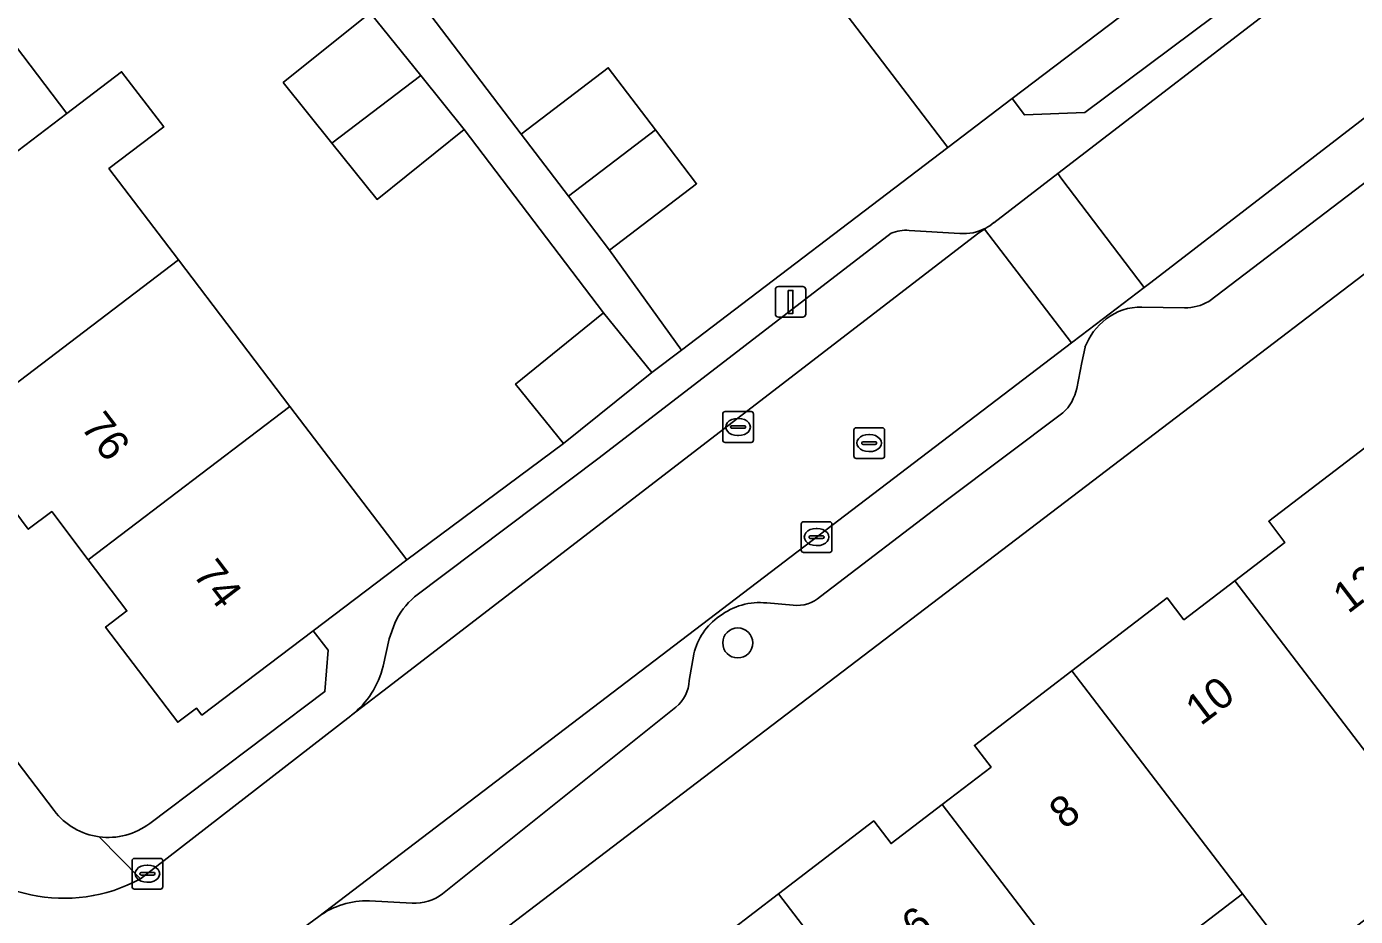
# Model space of a CAD drawing. Extents: x 160030 to 160839, y 385325 to 386450.
# Drawn here: x 160400.27 to 160443.58, y 385625.28 to 385654.28 of the extents above; entities that cross this region are included whole.
import ezdxf

# ---------------------------------------------------------------- set-up
doc = ezdxf.new("R2010")
doc.units = 0
for name, color, linetype in [('IMGEO_Boom', 7, 'Continuous'), ('IMGEO_Erf', 7, 'Continuous'), ('IMGEO_Kolk', 7, 'Continuous'), ('IMGEO_Lichtmast', 7, 'Continuous'), ('IMGEO_Muur', 7, 'Continuous'), ('IMGEO_Pand', 7, 'Continuous'), ('IMGEO_Pand_nummerreeks', 7, 'Continuous'), ('IMGEO_Parkeervlak_open', 7, 'Continuous'), ('IMGEO_Rijbaan_lokaal_open', 7, 'Continuous'), ('IMGEO_Rioolput', 7, 'Continuous'), ('IMGEO_Voetpad_open', 7, 'Continuous')]:
    doc.layers.add(name, color=color, linetype=linetype)

msp = doc.modelspace()

# ---------------------------------------------------------------- linework, layer by layer
at = {"layer": 'IMGEO_Boom'}
msp.add_circle((160423.447, 385634.193), 0.489, dxfattribs=at)
at = {"layer": 'IMGEO_Erf'}
for points in [[(160339.544, 385709.767), (160401.163, 385628.731)], [(160404.686, 385666.157), (160416.39, 385650.779), (160419.228, 385652.939), (160420.771, 385650.912), (160422.106, 385649.158), (160419.268, 385646.998), (160421.608, 385643.74), (160430.292, 385650.339), (160426.523, 385655.289)], [(160460.162, 385658.643), (160410.315, 385620.656)], [(160397.949, 385656.227), (160401.582, 385651.452), (160403.367, 385652.81), (160404.736, 385651.012), (160402.95, 385649.654), (160405.215, 385646.677), (160408.849, 385641.902), (160412.656, 385636.898), (160417.77, 385640.691), (160416.205, 385642.632), (160419.075, 385644.947), (160414.527, 385650.928), (160411.69, 385648.65), (160410.218, 385650.483), (160408.634, 385652.455), (160411.471, 385654.733)], [(160436.916, 385655.382), (160432.39, 385651.936), (160432.792, 385651.4), (160434.761, 385651.485), (160440.362, 385655.672)], [(160404.281, 385628.312), (160409.991, 385632.61), (160410.095, 385633.957), (160409.605, 385634.586), (160405.98, 385631.84), (160405.805, 385632.07), (160405.195, 385631.608), (160402.844, 385634.71), (160403.54, 385635.237), (160402.278, 385636.903), (160401.086, 385638.476), (160400.325, 385637.9), (160397.921, 385641.128), (160395.647, 385644.183), (160396.275, 385644.66), (160394.949, 385646.406), (160393.774, 385647.952), (160393.149, 385647.476), (160390.694, 385650.708), (160388.374, 385653.761), (160389.06, 385654.283)], [(160421.6, 385623.587), (160424.778, 385626.021), (160427.879, 385628.395), (160428.446, 385627.654), (160430.109, 385628.927), (160431.701, 385630.146), (160431.159, 385630.854), (160434.331, 385633.284), (160437.441, 385635.665), (160437.99, 385634.948), (160439.644, 385636.215), (160441.281, 385637.468), (160440.753, 385638.158), (160443.879, 385640.552)], [(160441.781, 385623.558), (160439.896, 385626.017), (160435.132, 385622.369)]]:
    msp.add_lwpolyline(points, dxfattribs=at)
for centre, radius, start, end in [((160402.934, 385630.08), 2.226, 217.296, 262.288), ((160402.931, 385630.075), 2.221, 262.3496, 307.4526)]:
    msp.add_arc(centre, radius, start, end, dxfattribs=at)
at = {"layer": 'IMGEO_Kolk'}
for p, q in [((160422.956, 385640.805), (160422.956, 385641.657)), ((160423.031, 385641.731), (160423.883, 385641.731)), ((160423.444, 385641.511), (160423.469, 385641.511)), ((160423.957, 385641.657), (160423.957, 385640.805)), ((160423.215, 385641.225), (160423.215, 385641.237)), ((160423.653, 385641.188), (160423.255, 385641.188)), ((160423.258, 385641.274), (160423.656, 385641.274)), ((160423.467, 385640.951), (160423.442, 385640.951)), ((160423.699, 385641.237), (160423.699, 385641.225)), ((160423.883, 385640.731), (160423.031, 385640.731)), ((160425.516, 385637.218), (160425.516, 385638.07)), ((160425.591, 385638.144), (160426.443, 385638.144)), ((160426.004, 385637.924), (160426.029, 385637.924)), ((160426.517, 385638.07), (160426.517, 385637.218)), ((160425.775, 385637.638), (160425.775, 385637.65)), ((160426.213, 385637.601), (160425.815, 385637.601)), ((160425.818, 385637.687), (160426.216, 385637.687)), ((160426.259, 385637.65), (160426.259, 385637.638)), ((160426.443, 385637.144), (160425.591, 385637.144)), ((160426.027, 385637.364), (160426.002, 385637.364)), ((160403.705, 385626.247), (160403.705, 385627.099)), ((160403.78, 385627.173), (160404.632, 385627.173)), ((160404.706, 385627.099), (160404.706, 385626.247)), ((160403.964, 385626.667), (160403.964, 385626.679)), ((160404.402, 385626.63), (160404.004, 385626.63)), ((160404.007, 385626.716), (160404.405, 385626.716)), ((160404.193, 385626.953), (160404.218, 385626.953)), ((160404.448, 385626.679), (160404.448, 385626.667)), ((160404.632, 385626.173), (160403.78, 385626.173)), ((160404.216, 385626.393), (160404.191, 385626.393))]:
    msp.add_line(p, q, dxfattribs=at)
for points in [[(160422.956, 385640.805), (160422.956, 385641.657)], [(160423.031, 385641.731), (160423.883, 385641.731)], [(160423.957, 385641.657), (160423.957, 385640.805)], [(160423.883, 385640.731), (160423.031, 385640.731)], [(160425.516, 385637.218), (160425.516, 385638.07)], [(160425.591, 385638.144), (160426.443, 385638.144)], [(160426.517, 385638.07), (160426.517, 385637.218)], [(160426.443, 385637.144), (160425.591, 385637.144)], [(160403.705, 385626.247), (160403.705, 385627.099)], [(160403.78, 385627.173), (160404.632, 385627.173)], [(160404.706, 385627.099), (160404.706, 385626.247)], [(160404.632, 385626.173), (160403.78, 385626.173)]]:
    msp.add_lwpolyline(points, dxfattribs=at)
for centre, radius, start, end in [((160423.033, 385641.655), 0.0765, 91.552, 178.448), ((160423.033, 385641.655), 0.0765, 91.552, 178.448), ((160423.881, 385641.655), 0.0765, 1.552, 88.448), ((160423.881, 385641.655), 0.0765, 1.552, 88.448), ((160423.255, 385641.234), 0.0403, 85.8775, 175.7526), ((160423.252, 385641.224), 0.0366, 178.938, 274.7102), ((160423.656, 385641.231), 0.043, 264.8664, 352.4533), ((160423.66, 385641.236), 0.0386, 1.7309, 96.639), ((160423.033, 385640.807), 0.0765, 181.552, 268.448), ((160423.033, 385640.807), 0.0765, 181.552, 268.448), ((160423.881, 385640.807), 0.0765, 271.552, 358.448), ((160423.881, 385640.807), 0.0765, 271.552, 358.448), ((160425.593, 385638.068), 0.0765, 91.552, 178.448), ((160425.593, 385638.068), 0.0765, 91.552, 178.448), ((160426.441, 385638.068), 0.0765, 1.552, 88.448), ((160426.441, 385638.068), 0.0765, 1.552, 88.448), ((160425.815, 385637.647), 0.0403, 85.8775, 175.7526), ((160425.812, 385637.637), 0.0366, 178.938, 274.7102), ((160426.216, 385637.644), 0.043, 264.8664, 352.4533), ((160426.22, 385637.649), 0.0386, 1.7309, 96.639), ((160425.593, 385637.22), 0.0765, 181.552, 268.448), ((160425.593, 385637.22), 0.0765, 181.552, 268.448), ((160426.441, 385637.22), 0.0765, 271.552, 358.448), ((160426.441, 385637.22), 0.0765, 271.552, 358.448), ((160403.782, 385627.097), 0.0765, 91.552, 178.448), ((160403.782, 385627.097), 0.0765, 91.552, 178.448), ((160404.63, 385627.097), 0.0765, 1.552, 88.448), ((160404.63, 385627.097), 0.0765, 1.552, 88.448), ((160404.004, 385626.676), 0.0403, 85.8775, 175.7526), ((160404.001, 385626.666), 0.0366, 178.938, 274.7102), ((160404.405, 385626.673), 0.043, 264.8664, 352.4533), ((160404.409, 385626.678), 0.0386, 1.7309, 96.639), ((160403.782, 385626.249), 0.0765, 181.552, 268.448), ((160403.782, 385626.249), 0.0765, 181.552, 268.448), ((160404.63, 385626.249), 0.0765, 271.552, 358.448), ((160404.63, 385626.249), 0.0765, 271.552, 358.448)]:
    msp.add_arc(centre, radius, start, end, dxfattribs=at)
for centre, major_axis, ratio, start_param, end_param in [((160423.443, 385641.231), (-0.387, 0.002), 0.722429, 4.712389, 7.853982), ((160423.468, 385641.231), (-0.39, 0.002), 0.717154, 1.570796, 4.712389), ((160426.003, 385637.644), (-0.387, 0.002), 0.722429, 4.712389, 7.853982), ((160426.028, 385637.644), (-0.39, 0.002), 0.717154, 1.570796, 4.712389), ((160404.192, 385626.673), (-0.387, 0.002), 0.722429, 4.712389, 7.853982), ((160404.217, 385626.673), (-0.39, 0.002), 0.717154, 1.570796, 4.712389)]:
    msp.add_ellipse(centre, major_axis=major_axis, ratio=ratio, start_param=start_param, end_param=end_param, dxfattribs=at)
at = {"layer": 'IMGEO_Lichtmast'}
for p, q in [((160424.673, 385644.909), (160424.673, 385645.709)), ((160424.673, 385645.709), (160424.673, 385644.909)), ((160424.773, 385645.809), (160425.563, 385645.809)), ((160425.563, 385645.809), (160424.773, 385645.809)), ((160425.663, 385645.709), (160425.663, 385644.909)), ((160425.663, 385644.909), (160425.663, 385645.709)), ((160425.563, 385644.809), (160424.773, 385644.809)), ((160424.773, 385644.809), (160425.563, 385644.809))]:
    msp.add_line(p, q, dxfattribs=at)
msp.add_lwpolyline([(160425.093, 385645.684), (160425.243, 385645.684), (160425.243, 385644.934), (160425.093, 385644.934), (160425.093, 385645.684)], dxfattribs=at)
for centre, start, end in [((160424.773, 385645.709), 90, 180), ((160424.773, 385645.709), 90, 180), ((160425.563, 385645.709), 0, 90), ((160425.563, 385645.709), 360, 90), ((160424.773, 385644.909), 180, 270), ((160424.773, 385644.909), 180, 270), ((160425.563, 385644.909), 270, 0), ((160425.563, 385644.909), 270, 0)]:
    msp.add_arc(centre, 0.1, start, end, dxfattribs=at)
at = {"layer": 'IMGEO_Muur'}
for points in [[(160421.608, 385643.74), (160430.292, 385650.339)], [(160417.77, 385640.691), (160412.656, 385636.898)]]:
    msp.add_lwpolyline(points, dxfattribs=at)
at = {"layer": 'IMGEO_Pand'}
for points in [[(160432.39, 385651.936), (160436.916, 385655.382), (160436.749, 385655.601), (160437.372, 385656.075), (160435.044, 385659.132), (160434.237, 385658.518), (160432.964, 385660.191), (160426.523, 385655.289), (160430.292, 385650.339)], [(160390.694, 385650.708), (160393.149, 385647.476), (160393.774, 385647.952), (160394.949, 385646.406), (160401.582, 385651.452), (160397.949, 385656.227)], [(160411.471, 385654.733), (160408.634, 385652.455), (160410.218, 385650.483), (160413.114, 385652.687)], [(160405.215, 385646.677), (160402.95, 385649.654), (160404.736, 385651.012), (160403.367, 385652.81), (160401.582, 385651.452), (160394.949, 385646.406), (160396.275, 385644.66), (160395.647, 385644.183), (160397.921, 385641.128)], [(160411.69, 385648.65), (160414.527, 385650.928), (160413.114, 385652.687), (160410.218, 385650.483)], [(160420.771, 385650.912), (160419.228, 385652.939), (160416.39, 385650.779), (160417.933, 385648.752)], [(160420.771, 385650.912), (160417.933, 385648.752), (160419.268, 385646.998), (160422.106, 385649.158)], [(160397.921, 385641.128), (160400.325, 385637.9), (160401.086, 385638.476), (160402.278, 385636.903), (160408.849, 385641.902), (160405.215, 385646.677)], [(160420.641, 385643.006), (160419.075, 385644.947), (160416.205, 385642.632), (160417.77, 385640.691)], [(160412.656, 385636.898), (160408.849, 385641.902), (160402.278, 385636.903), (160403.54, 385635.237), (160402.844, 385634.71), (160405.195, 385631.608), (160405.805, 385632.07), (160405.98, 385631.84), (160409.605, 385634.586)], [(160449.423, 385633.312), (160443.879, 385640.552), (160440.753, 385638.158), (160441.281, 385637.468), (160439.644, 385636.215), (160444.66, 385629.665)], [(160437.99, 385634.948), (160437.441, 385635.665), (160434.331, 385633.284), (160439.896, 385626.017), (160441.781, 385623.558), (160446.544, 385627.205), (160444.66, 385629.665), (160439.644, 385636.215)], [(160439.896, 385626.017), (160434.331, 385633.284), (160431.159, 385630.854), (160431.701, 385630.146), (160430.109, 385628.927), (160435.132, 385622.369)], [(160435.132, 385622.369), (160430.109, 385628.927), (160428.446, 385627.654), (160427.879, 385628.395), (160424.778, 385626.021), (160430.368, 385618.721)], [(160424.778, 385626.021), (160421.6, 385623.587), (160422.204, 385622.798), (160420.619, 385621.585), (160425.604, 385615.074), (160427.139, 385613.069), (160431.903, 385616.717), (160430.368, 385618.721)]]:
    msp.add_lwpolyline(points, close=True, dxfattribs=at)
at = {"layer": 'IMGEO_Parkeervlak_open'}
for points in [[(160447.596, 385654.17), (160436.906, 385645.942), (160436.696, 385645.782), (160434.639, 385644.215), (160434.322, 385643.974), (160409.789, 385625.281)], [(160438.797, 385645.324), (160446.86, 385651.459)], [(160410.858, 385631.839), (160411.883, 385632.627), (160431.304, 385647.559), (160431.485, 385647.681)], [(160428.445, 385647.548), (160418.935, 385640.223), (160412.91, 385635.694)], [(160430.685, 385647.538), (160429.033, 385647.639)], [(160431.485, 385647.681), (160431.527, 385647.709)], [(160436.619, 385645.137), (160438.011, 385645.118)], [(160434.493, 385642.488), (160434.659, 385643.332), (160434.764, 385643.83)], [(160426.142, 385635.709), (160430.242, 385638.841), (160434.038, 385641.69)], [(160424.394, 385635.498), (160425.253, 385635.428)], [(160412.267, 385634.841), (160412.086, 385634.326), (160411.892, 385633.441)], [(160421.864, 385632.967), (160422.019, 385633.833)], [(160413.828, 385626.02), (160421.431, 385632.101)], [(160411.441, 385625.789), (160412.835, 385625.713)]]:
    msp.add_lwpolyline(points, dxfattribs=at)
for centre, radius, start, end in [((160428.944, 385646.267), 1.375, 86.2988, 111.296), ((160430.815, 385649.056), 1.523, 265.1009, 297.859), ((160438.051, 385646.568), 1.451, 268.4237, 300.9486), ((160436.577, 385643.3), 1.838, 88.6797, 127.6883), ((160436.787, 385643.04), 2.172, 127.9028, 158.6755), ((160433.051, 385642.782), 1.472, 312.1282, 348.4903), ((160425.403, 385636.499), 1.081, 261.9997, 313.0823), ((160414.537, 385633.799), 2.497, 130.6411, 155.3402), ((160424.17, 385633.329), 2.18, 84.1132, 127.2374), ((160424.006, 385633.388), 2.037, 124.5608, 167.375), ((160409.095, 385634.112), 2.876, 307.8038, 346.5163), ((160420.688, 385633.014), 1.177, 309.1556, 357.7143), ((160411.36, 385623.113), 2.677, 88.2632, 125.9228), ((160412.915, 385627.214), 1.503, 266.9576, 307.4019)]:
    msp.add_arc(centre, radius, start, end, dxfattribs=at)
at = {"layer": 'IMGEO_Rijbaan_lokaal_open'}
for points in [[(160442.4, 385656.222), (160441.798, 385655.588), (160433.875, 385649.49), (160434.013, 385649.307), (160436.696, 385645.782), (160436.906, 385645.942), (160447.596, 385654.17)], [(160431.527, 385647.709), (160431.485, 385647.681), (160434.322, 385643.974), (160434.639, 385644.215), (160436.696, 385645.782), (160434.013, 385649.307), (160433.875, 385649.49)], [(160433.875, 385649.49), (160431.795, 385647.89)], [(160434.322, 385643.974), (160431.485, 385647.681), (160431.304, 385647.559), (160411.883, 385632.627), (160410.858, 385631.839), (160410.832, 385631.819), (160403.978, 385626.504)], [(160406.576, 385622.919), (160409.789, 385625.281), (160434.322, 385643.974)]]:
    msp.add_lwpolyline(points, dxfattribs=at)
for centre, radius, start, end in [((160430.852, 385648.998), 1.455, 297.6528, 310.4152), ((160401.482, 385631.116), 5.244, 217.9348, 298.4237)]:
    msp.add_arc(centre, radius, start, end, dxfattribs=at)
at = {"layer": 'IMGEO_Rioolput'}
for p, q in [((160427.229, 385640.282), (160427.229, 385641.134)), ((160427.304, 385641.208), (160428.156, 385641.208)), ((160427.717, 385640.988), (160427.742, 385640.988)), ((160428.23, 385641.134), (160428.23, 385640.282)), ((160427.488, 385640.702), (160427.488, 385640.714)), ((160427.926, 385640.665), (160427.528, 385640.665)), ((160427.531, 385640.751), (160427.929, 385640.751)), ((160427.972, 385640.714), (160427.972, 385640.702)), ((160428.156, 385640.208), (160427.304, 385640.208)), ((160427.74, 385640.428), (160427.715, 385640.428))]:
    msp.add_line(p, q, dxfattribs=at)
for points in [[(160427.229, 385640.282), (160427.229, 385641.134)], [(160427.304, 385641.208), (160428.156, 385641.208)], [(160428.23, 385641.134), (160428.23, 385640.282)], [(160428.156, 385640.208), (160427.304, 385640.208)]]:
    msp.add_lwpolyline(points, dxfattribs=at)
for centre, radius, start, end in [((160427.306, 385641.132), 0.0765, 91.552, 178.448), ((160427.306, 385641.132), 0.0765, 91.552, 178.448), ((160428.154, 385641.132), 0.0765, 1.552, 88.448), ((160428.154, 385641.132), 0.0765, 1.552, 88.448), ((160427.528, 385640.711), 0.0403, 85.8775, 175.7526), ((160427.525, 385640.701), 0.0366, 178.938, 274.7102), ((160427.929, 385640.708), 0.043, 264.8664, 352.4533), ((160427.933, 385640.713), 0.0386, 1.7309, 96.639), ((160427.306, 385640.284), 0.0765, 181.552, 268.448), ((160427.306, 385640.284), 0.0765, 181.552, 268.448), ((160428.154, 385640.284), 0.0765, 271.552, 358.448), ((160428.154, 385640.284), 0.0765, 271.552, 358.448)]:
    msp.add_arc(centre, radius, start, end, dxfattribs=at)
for centre, major_axis, ratio, start_param, end_param in [((160427.716, 385640.708), (-0.387, 0.002), 0.722429, 4.712389, 7.853982), ((160427.741, 385640.708), (-0.39, 0.002), 0.717154, 1.570796, 4.712389)]:
    msp.add_ellipse(centre, major_axis=major_axis, ratio=ratio, start_param=start_param, end_param=end_param, dxfattribs=at)
at = {"layer": 'IMGEO_Voetpad_open'}
for points in [[(160401.163, 385628.731), (160339.544, 385709.767)], [(160411.471, 385654.733), (160413.114, 385652.687), (160414.527, 385650.928), (160419.075, 385644.947), (160420.641, 385643.006), (160421.608, 385643.74), (160419.268, 385646.998), (160417.933, 385648.752), (160416.39, 385650.779), (160404.686, 385666.157)], [(160410.315, 385620.656), (160460.162, 385658.643)], [(160440.362, 385655.672), (160434.761, 385651.485), (160432.792, 385651.4), (160432.39, 385651.936), (160430.292, 385650.339), (160421.608, 385643.74), (160420.641, 385643.006), (160417.77, 385640.691), (160412.656, 385636.898), (160409.605, 385634.586), (160410.095, 385633.957), (160409.991, 385632.61), (160404.281, 385628.312)], [(160431.795, 385647.89), (160433.875, 385649.49), (160441.798, 385655.588)], [(160446.86, 385651.459), (160438.797, 385645.324)], [(160412.91, 385635.694), (160418.935, 385640.223), (160428.445, 385647.548)], [(160429.033, 385647.639), (160430.685, 385647.538)], [(160438.011, 385645.118), (160436.619, 385645.137)], [(160434.764, 385643.83), (160434.659, 385643.332), (160434.493, 385642.488)], [(160434.038, 385641.69), (160430.242, 385638.841), (160426.142, 385635.709)], [(160425.253, 385635.428), (160424.394, 385635.498)], [(160411.892, 385633.441), (160412.086, 385634.326), (160412.267, 385634.841)], [(160422.019, 385633.833), (160421.864, 385632.967)], [(160402.635, 385627.874), (160403.978, 385626.504), (160410.832, 385631.819), (160410.858, 385631.839)], [(160421.431, 385632.101), (160413.828, 385626.02)], [(160403.978, 385626.504), (160402.635, 385627.874)], [(160412.835, 385625.713), (160411.441, 385625.789)]]:
    msp.add_lwpolyline(points, dxfattribs=at)
for centre, radius, start, end in [((160430.852, 385648.998), 1.455, 297.6528, 310.4152), ((160428.944, 385646.267), 1.375, 86.2988, 111.296), ((160430.815, 385649.056), 1.523, 265.1009, 297.859), ((160438.051, 385646.568), 1.451, 268.4237, 300.9486), ((160436.577, 385643.3), 1.838, 88.6797, 127.6883), ((160436.787, 385643.04), 2.172, 127.9028, 158.6755), ((160433.051, 385642.782), 1.472, 312.1282, 348.4903), ((160425.403, 385636.499), 1.081, 261.9997, 313.0823), ((160414.537, 385633.799), 2.497, 130.6411, 155.3402), ((160424.17, 385633.329), 2.18, 84.1132, 127.2374), ((160424.006, 385633.388), 2.037, 124.5608, 167.375), ((160409.095, 385634.112), 2.876, 307.8038, 346.5163), ((160420.688, 385633.014), 1.177, 309.1556, 357.7143), ((160402.934, 385630.08), 2.226, 217.296, 262.288), ((160402.931, 385630.075), 2.221, 262.3496, 307.4526), ((160401.482, 385631.116), 5.244, 217.9348, 298.4237), ((160411.36, 385623.113), 2.677, 88.2632, 125.9228), ((160412.915, 385627.214), 1.503, 266.9576, 307.4019)]:
    msp.add_arc(centre, radius, start, end, dxfattribs=at)

# ---------------------------------------------------------------- texts
at = {"layer": 'IMGEO_Pand_nummerreeks'}
for s, rotation, p in [('76', 307.2538, (160402.005, 385641.229)), ('74', 307.2538, (160405.659, 385636.425)), ('12', 37.2507, (160443.339, 385635.125)), ('10', 37.2507, (160438.535, 385631.472)), ('8', 37.2507, (160434.094, 385628.094)), ('6', 37.2507, (160429.28, 385624.434))]:
    msp.add_text(s, height=1, rotation=rotation, dxfattribs=at).set_placement(p)

doc.saveas('drawing.dxf')
